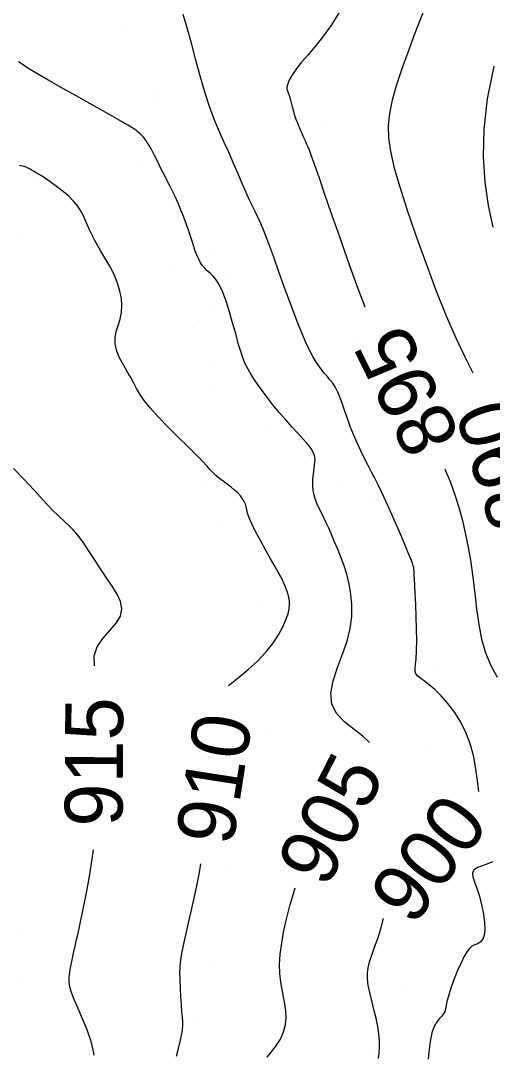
# Model space of a CAD drawing. Extents: x 400243 to 403697, y 4403637 to 4408083.
# Drawn here: x 402798.8 to 402859.8, y 4405855.9 to 4405990.3 of the extents above; entities that cross this region are included whole.
import ezdxf

# ---------------------------------------------------------------- set-up
doc = ezdxf.new("R2010")
doc.units = 0
doc.layers.add('HH_IC', color=7, linetype='Continuous')

msp = doc.modelspace()

# ---------------------------------------------------------------- linework, layer by layer
at = {"layer": 'HH_IC'}
for p, q in [((402812.27, 4405988.94), (402812.27, 4405988.94)), ((402816.11, 4405980.93), (402816.11, 4405980.93)), ((402815.81, 4405979.95), (402815.81, 4405979.95)), ((402838.18, 4405977.03), (402838.18, 4405977.03)), ((402814.25, 4405971.9), (402814.25, 4405971.9)), ((402818.19, 4405970.9), (402818.19, 4405970.9)), ((402800.36, 4405969.95), (402800.36, 4405969.95)), ((402818.38, 4405966.59), (402818.38, 4405966.59)), ((402799.14, 4405962.19), (402799.14, 4405962.19)), ((402823.27, 4405959.95), (402823.27, 4405959.95)), ((402818.45, 4405958.62), (402818.45, 4405958.62)), ((402825.28, 4405957.48), (402825.28, 4405957.48)), ((402823.89, 4405952.9), (402823.89, 4405952.9)), ((402821.03, 4405950.54), (402821.03, 4405950.54)), ((402842.61, 4405948.63), (402842.61, 4405948.63)), ((402823.74, 4405945.88), (402823.74, 4405945.88)), ((402827.64, 4405944.76), (402827.64, 4405944.76)), ((402823.91, 4405942.35), (402823.91, 4405942.35)), ((402830.4, 4405937.76), (402830.4, 4405937.76)), ((402836.25, 4405934.4), (402836.25, 4405934.4)), ((402836.43, 4405933.89), (402836.43, 4405933.89)), ((402822.29, 4405930.07), (402822.29, 4405930.07)), ((402840.28, 4405930.62), (402840.28, 4405930.62)), ((402844.25, 4405927.85), (402844.25, 4405927.85)), ((402824.75, 4405925.05), (402824.75, 4405925.05)), ((402849.34, 4405919.6), (402849.34, 4405919.6)), ((402829.84, 4405914.78), (402829.84, 4405914.78)), ((402852.03, 4405906.66), (402852.03, 4405906.66)), ((402830.64, 4405898.69), (402830.64, 4405898.69)), ((402851.82, 4405896.2), (402851.82, 4405896.2)), ((402854.65, 4405887.27), (402854.65, 4405887.27)), ((402853.82, 4405881.5), (402853.82, 4405881.5)), ((402825.87, 4405881.03), (402825.87, 4405881.03)), ((402852.28, 4405874.06), (402852.28, 4405874.06)), ((402799.03, 4405872.77), (402799.03, 4405872.77)), ((402824, 4405868.48), (402824, 4405868.48)), ((402798.89, 4405866.14), (402798.89, 4405866.14)), ((402848.24, 4405865.54), (402848.24, 4405865.54)), ((402821.33, 4405860.55), (402821.33, 4405860.55)), ((402843.88, 4405856.71), (402843.88, 4405856.71))]:
    msp.add_line(p, q, dxfattribs=at)
for points in [[(402858.07, 4405890.54), (402857.93, 4405891.93), (402857.72, 4405893.43), (402857.42, 4405894.99), (402857.01, 4405896.55), (402856.46, 4405898.07), (402855.76, 4405899.48), (402854.96, 4405900.76), (402854.09, 4405901.91), (402853.23, 4405902.89), (402852.41, 4405903.7), (402851.68, 4405904.33), (402851.06, 4405904.8), (402850.56, 4405905.16), (402850.18, 4405905.46), (402849.94, 4405905.74), (402849.83, 4405906.04), (402849.83, 4405906.42), (402849.89, 4405906.95), (402849.97, 4405907.7), (402850.04, 4405908.72), (402850.06, 4405910.04), (402850.04, 4405911.58), (402849.98, 4405913.18), (402849.92, 4405914.74), (402849.85, 4405916.1), (402849.8, 4405917.17), (402849.76, 4405917.98), (402849.73, 4405918.56), (402849.7, 4405918.97), (402849.68, 4405919.27), (402849.66, 4405919.5), (402849.6, 4405919.74), (402849.49, 4405920.08), (402849.29, 4405920.61), (402848.96, 4405921.4), (402848.5, 4405922.5), (402847.94, 4405923.84), (402847.31, 4405925.3), (402846.67, 4405926.75), (402846.07, 4405928.09), (402845.54, 4405929.22), (402845.06, 4405930.19), (402844.62, 4405931.05), (402844.2, 4405931.86), (402843.76, 4405932.71), (402843.29, 4405933.63), (402842.81, 4405934.62), (402842.33, 4405935.65), (402841.87, 4405936.7), (402841.45, 4405937.75), (402841.09, 4405938.77), (402840.76, 4405939.74), (402840.45, 4405940.65), (402840.15, 4405941.47), (402839.85, 4405942.2), (402839.52, 4405942.82), (402839.17, 4405943.35), (402838.82, 4405943.81), (402838.45, 4405944.25), (402838.08, 4405944.67), (402837.72, 4405945.12), (402837.36, 4405945.61), (402836.98, 4405946.17), (402836.59, 4405946.83), (402836.18, 4405947.62), (402835.74, 4405948.55), (402835.26, 4405949.64), (402834.74, 4405950.91), (402834.17, 4405952.36), (402833.56, 4405954), (402832.9, 4405955.83), (402832.21, 4405957.76), (402831.54, 4405959.65), (402830.9, 4405961.39), (402830.35, 4405962.87), (402829.88, 4405964), (402829.49, 4405964.86), (402829.14, 4405965.58), (402828.79, 4405966.27), (402828.41, 4405967.06), (402827.97, 4405968.04), (402827.47, 4405969.18), (402826.92, 4405970.44), (402826.35, 4405971.78), (402825.75, 4405973.15), (402825.13, 4405974.51), (402824.51, 4405975.9), (402823.89, 4405977.4), (402823.26, 4405979.04), (402822.65, 4405980.88), (402822.04, 4405982.96), (402821.45, 4405985.16), (402820.88, 4405987.34), (402820.33, 4405989.36), (402819.81, 4405991.06)], [(402840, 4405991.33), (402838.92, 4405989.61), (402837.85, 4405988.14), (402836.85, 4405986.89), (402835.93, 4405985.82), (402835.15, 4405984.9), (402834.52, 4405984.1), (402834.04, 4405983.41), (402833.68, 4405982.82), (402833.44, 4405982.34), (402833.3, 4405981.95), (402833.24, 4405981.65), (402833.24, 4405981.41), (402833.3, 4405981.18), (402833.4, 4405980.92), (402833.52, 4405980.59), (402833.65, 4405980.16), (402833.79, 4405979.65), (402833.93, 4405979.1), (402834.08, 4405978.54), (402834.24, 4405978.01), (402834.39, 4405977.54), (402834.55, 4405977.13), (402834.71, 4405976.75), (402834.87, 4405976.39), (402835.02, 4405976.05), (402835.18, 4405975.7), (402835.32, 4405975.36), (402835.46, 4405975.04), (402835.59, 4405974.75), (402835.7, 4405974.5), (402835.8, 4405974.29), (402835.92, 4405974.01), (402836.11, 4405973.55), (402836.4, 4405972.79), (402836.82, 4405971.6), (402837.41, 4405969.92), (402838.13, 4405967.83), (402838.95, 4405965.46), (402839.82, 4405962.95), (402840.7, 4405960.42), (402841.55, 4405957.98), (402842.41, 4405955.6), (402843.32, 4405953.24)], [(402850.87, 4405991.37), (402849.82, 4405988.66), (402848.88, 4405986.17), (402848.07, 4405983.9), (402847.4, 4405981.84), (402846.89, 4405979.97), (402846.54, 4405978.27), (402846.37, 4405976.69), (402846.4, 4405975.11), (402846.64, 4405973.39), (402847.1, 4405971.36), (402847.81, 4405968.89), (402848.77, 4405965.88), (402849.93, 4405962.48), (402851.21, 4405958.91), (402852.54, 4405955.38), (402853.86, 4405952.09), (402855.11, 4405949.23), (402856.27, 4405946.78), (402857.32, 4405944.68)], [(402843.93, 4405896.87), (402843.06, 4405897.69), (402841.93, 4405898.55), (402840.75, 4405899.5), (402839.72, 4405900.57), (402839.07, 4405901.82), (402838.94, 4405903.26), (402839.24, 4405904.86), (402839.8, 4405906.55), (402840.45, 4405908.28), (402841.04, 4405909.99), (402841.44, 4405911.63), (402841.63, 4405913.18), (402841.65, 4405914.66), (402841.53, 4405916.07), (402841.3, 4405917.4), (402840.98, 4405918.66), (402840.61, 4405919.85), (402840.2, 4405920.96), (402839.78, 4405921.98), (402839.38, 4405922.93), (402839, 4405923.79), (402838.66, 4405924.58), (402838.34, 4405925.3), (402838.03, 4405925.95), (402837.73, 4405926.57), (402837.44, 4405927.14), (402837.17, 4405927.7), (402836.94, 4405928.26), (402836.75, 4405928.85), (402836.64, 4405929.48), (402836.6, 4405930.18), (402836.62, 4405930.91), (402836.68, 4405931.62), (402836.76, 4405932.26), (402836.82, 4405932.8), (402836.86, 4405933.2), (402836.88, 4405933.48), (402836.87, 4405933.68), (402836.84, 4405933.83), (402836.8, 4405933.98), (402836.75, 4405934.16), (402836.66, 4405934.38), (402836.5, 4405934.68), (402836.24, 4405935.06), (402835.86, 4405935.55), (402835.32, 4405936.17), (402834.65, 4405936.89), (402833.9, 4405937.71), (402833.09, 4405938.6), (402832.25, 4405939.57), (402831.43, 4405940.57), (402830.64, 4405941.59), (402829.9, 4405942.59), (402829.24, 4405943.54), (402828.68, 4405944.4), (402828.23, 4405945.16), (402827.86, 4405945.87), (402827.55, 4405946.62), (402827.26, 4405947.47), (402826.95, 4405948.51), (402826.61, 4405949.77), (402826.22, 4405951.17), (402825.82, 4405952.61), (402825.39, 4405953.98), (402824.95, 4405955.15), (402824.52, 4405956.06), (402824.09, 4405956.73), (402823.68, 4405957.22), (402823.29, 4405957.59), (402822.93, 4405957.91), (402822.61, 4405958.23), (402822.33, 4405958.56), (402822.06, 4405958.95), (402821.82, 4405959.4), (402821.58, 4405959.94), (402821.34, 4405960.59), (402821.1, 4405961.33), (402820.84, 4405962.14), (402820.56, 4405963.01), (402820.25, 4405963.91), (402819.9, 4405964.84), (402819.53, 4405965.76), (402819.15, 4405966.66), (402818.76, 4405967.51), (402818.39, 4405968.3), (402818.04, 4405969), (402817.71, 4405969.64), (402817.39, 4405970.26), (402817.06, 4405970.88), (402816.74, 4405971.54), (402816.39, 4405972.26), (402816.03, 4405973.01), (402815.64, 4405973.76), (402815.2, 4405974.48), (402814.72, 4405975.13), (402814.17, 4405975.69), (402813.5, 4405976.21), (402812.64, 4405976.76), (402811.53, 4405977.41), (402810.1, 4405978.2), (402808.32, 4405979.19), (402806.34, 4405980.31), (402804.32, 4405981.46), (402802.43, 4405982.54), (402800.85, 4405983.45), (402799.71, 4405984.14), (402798.95, 4405984.62), (402798.48, 4405984.94)], [(402859.94, 4405963.54), (402859.36, 4405966.35), (402858.92, 4405969.38), (402858.7, 4405972.65), (402858.78, 4405976.23), (402859.22, 4405980.14), (402860.07, 4405984.37)], [(402825.68, 4405904.25), (402826.93, 4405905.24), (402828.22, 4405906.29), (402829.45, 4405907.39), (402830.52, 4405908.53), (402831.41, 4405909.67), (402832.14, 4405910.78), (402832.7, 4405911.81), (402833.12, 4405912.73), (402833.39, 4405913.5), (402833.54, 4405914.16), (402833.59, 4405914.71), (402833.57, 4405915.18), (402833.5, 4405915.61), (402833.4, 4405916.02), (402833.28, 4405916.39), (402833.15, 4405916.75), (402833.01, 4405917.08), (402832.88, 4405917.38), (402832.76, 4405917.66), (402832.61, 4405917.98), (402832.41, 4405918.38), (402832.11, 4405918.92), (402831.69, 4405919.67), (402831.13, 4405920.65), (402830.48, 4405921.8), (402829.82, 4405922.99), (402829.19, 4405924.15), (402828.69, 4405925.16), (402828.35, 4405925.94), (402828.15, 4405926.54), (402828.04, 4405926.99), (402827.96, 4405927.36), (402827.87, 4405927.69), (402827.72, 4405928.04), (402827.5, 4405928.4), (402827.23, 4405928.77), (402826.88, 4405929.15), (402826.47, 4405929.53), (402826.01, 4405929.91), (402825.5, 4405930.29), (402824.99, 4405930.67), (402824.5, 4405931.04), (402824.06, 4405931.4), (402823.68, 4405931.76), (402823.31, 4405932.16), (402822.86, 4405932.66), (402822.27, 4405933.3), (402821.46, 4405934.14), (402820.38, 4405935.2), (402819.14, 4405936.43), (402817.83, 4405937.72), (402816.59, 4405938.99), (402815.54, 4405940.15), (402814.76, 4405941.12), (402814.2, 4405941.94), (402813.79, 4405942.68), (402813.43, 4405943.38), (402813.05, 4405944.1), (402812.58, 4405944.89), (402812.07, 4405945.75), (402811.59, 4405946.63), (402811.21, 4405947.52), (402811, 4405948.39), (402811, 4405949.22), (402811.16, 4405950.03), (402811.41, 4405950.83), (402811.66, 4405951.65), (402811.84, 4405952.5), (402811.88, 4405953.4), (402811.81, 4405954.33), (402811.63, 4405955.26), (402811.37, 4405956.16), (402811.06, 4405957.01), (402810.71, 4405957.77), (402810.34, 4405958.48), (402809.95, 4405959.15), (402809.56, 4405959.8), (402809.16, 4405960.46), (402808.77, 4405961.14), (402808.39, 4405961.84), (402808.03, 4405962.53), (402807.7, 4405963.22), (402807.4, 4405963.88), (402807.13, 4405964.51), (402806.85, 4405965.11), (402806.54, 4405965.7), (402806.16, 4405966.28), (402805.67, 4405966.88), (402805.04, 4405967.5), (402804.33, 4405968.11), (402803.59, 4405968.68), (402802.9, 4405969.2), (402802.3, 4405969.62), (402801.86, 4405969.92), (402801.54, 4405970.13), (402801.32, 4405970.27), (402801.16, 4405970.37), (402801.01, 4405970.45), (402800.85, 4405970.54), (402800.69, 4405970.63), (402800.51, 4405970.73), (402800.34, 4405970.83), (402800.17, 4405970.94), (402800.01, 4405971.04), (402799.85, 4405971.14), (402799.67, 4405971.23), (402799.47, 4405971.31), (402799.23, 4405971.39), (402798.95, 4405971.45), (402798.62, 4405971.51)], [(402808.32, 4405906.8), (402808.27, 4405908.08), (402808.68, 4405909.25), (402809.43, 4405910.33), (402810.31, 4405911.34), (402811.13, 4405912.3), (402811.71, 4405913.23), (402811.89, 4405914.16), (402811.72, 4405915.09), (402811.27, 4405916.06), (402810.64, 4405917.08), (402809.89, 4405918.17), (402809.11, 4405919.34), (402808.33, 4405920.54), (402807.57, 4405921.71), (402806.85, 4405922.78), (402806.19, 4405923.68), (402805.59, 4405924.37), (402805.02, 4405924.95), (402804.41, 4405925.51), (402803.7, 4405926.17), (402802.82, 4405927.03), (402801.74, 4405928.17), (402800.51, 4405929.51), (402799.19, 4405930.92), (402797.86, 4405932.3)], [(402853.67, 4405932.25), (402854.36, 4405930.62), (402854.94, 4405929.04), (402855.45, 4405927.44), (402855.92, 4405925.76), (402856.34, 4405923.99), (402856.72, 4405922.13), (402857.05, 4405920.21), (402857.33, 4405918.22), (402857.56, 4405916.19), (402857.79, 4405914.15), (402858.07, 4405912.15), (402858.44, 4405910.24), (402858.95, 4405908.45), (402859.65, 4405906.82), (402860.46, 4405905.32)], [(402808.29, 4405856.42), (402808.26, 4405856.72), (402807.91, 4405858.19), (402807.39, 4405859.68), (402806.8, 4405861.12), (402806.22, 4405862.44), (402805.72, 4405863.59), (402805.37, 4405864.51), (402805.16, 4405865.26), (402805.06, 4405865.9), (402805.07, 4405866.51), (402805.14, 4405867.16), (402805.27, 4405867.91), (402805.43, 4405868.73), (402805.62, 4405869.6), (402805.82, 4405870.49), (402806.02, 4405871.36), (402806.21, 4405872.19), (402806.39, 4405873.01), (402806.58, 4405873.89), (402806.78, 4405874.85), (402807, 4405875.94), (402807.24, 4405877.2), (402807.5, 4405878.59), (402807.76, 4405880.05), (402808, 4405881.52), (402808.2, 4405882.96)], [(402818.95, 4405856.29), (402819.14, 4405856.94), (402819.48, 4405858.35), (402819.68, 4405859.39), (402819.77, 4405860.14), (402819.78, 4405860.74), (402819.73, 4405861.32), (402819.65, 4405862.01), (402819.58, 4405862.91), (402819.51, 4405863.96), (402819.45, 4405865.07), (402819.42, 4405866.13), (402819.4, 4405867.06), (402819.41, 4405867.79), (402819.45, 4405868.41), (402819.54, 4405869.03), (402819.7, 4405869.79), (402819.92, 4405870.8), (402820.21, 4405872.14), (402820.56, 4405873.71), (402820.92, 4405875.36), (402821.27, 4405876.95), (402821.57, 4405878.33), (402821.8, 4405879.41), (402821.96, 4405880.3), (402822.09, 4405881.17)], [(402859.91, 4405881.42), (402858.79, 4405881.01), (402857.93, 4405880.68), (402857.43, 4405880.34), (402857.25, 4405879.95), (402857.31, 4405879.46), (402857.53, 4405878.83), (402857.84, 4405878.01), (402858.16, 4405876.99), (402858.45, 4405875.84), (402858.68, 4405874.66), (402858.84, 4405873.55), (402858.88, 4405872.61), (402858.79, 4405871.9), (402858.59, 4405871.41), (402858.32, 4405871.08), (402858.02, 4405870.87), (402857.71, 4405870.74), (402857.43, 4405870.62), (402857.15, 4405870.46), (402856.87, 4405870.21), (402856.56, 4405869.81), (402856.2, 4405869.2), (402855.79, 4405868.36), (402855.34, 4405867.34), (402854.9, 4405866.26), (402854.5, 4405865.19), (402854.2, 4405864.23), (402854, 4405863.46), (402853.88, 4405862.86), (402853.79, 4405862.4), (402853.69, 4405862.03), (402853.53, 4405861.74), (402853.29, 4405861.46), (402852.98, 4405861.15), (402852.64, 4405860.73), (402852.3, 4405860.13), (402852.01, 4405859.29), (402851.78, 4405858.16), (402851.61, 4405856.8), (402851.52, 4405855.88)], [(402830.7, 4405856.14), (402831.08, 4405856.61), (402831.82, 4405857.56), (402832.42, 4405858.49), (402832.82, 4405859.41), (402833.05, 4405860.32), (402833.13, 4405861.23), (402833.09, 4405862.13), (402832.97, 4405863.03), (402832.8, 4405863.94), (402832.61, 4405864.88), (402832.44, 4405865.87), (402832.33, 4405866.95), (402832.3, 4405868.15), (402832.39, 4405869.48), (402832.57, 4405870.89), (402832.82, 4405872.31), (402833.11, 4405873.66), (402833.41, 4405874.87), (402833.68, 4405875.89), (402833.93, 4405876.74), (402834.13, 4405877.45), (402834.29, 4405878.07)], [(402845.09, 4405855.96), (402845.17, 4405856.6), (402845.22, 4405857.4), (402845.22, 4405858.25), (402845.15, 4405859.15), (402845, 4405860.13), (402844.78, 4405861.21), (402844.51, 4405862.33), (402844.22, 4405863.45), (402843.97, 4405864.51), (402843.77, 4405865.47), (402843.67, 4405866.29), (402843.67, 4405867.01), (402843.77, 4405867.72), (402843.95, 4405868.47), (402844.23, 4405869.33), (402844.59, 4405870.36), (402845, 4405871.52), (402845.39, 4405872.77), (402845.73, 4405874.07)]]:
    msp.add_lwpolyline(points, dxfattribs=at)

# ---------------------------------------------------------------- texts
for s, rotation, p in [('895', 116.2575, (402855.8, 4405936.42)), ('890', 107.2282, (402867.08, 4405925.88)), ('915', 89.7184, (402811.97, 4405885.96)), ('910', 81.1562, (402826.22, 4405883.34)), ('905', 62.8576, (402838.38, 4405877.83)), ('900', 53.1695, (402849.56, 4405872.93))]:
    msp.add_text(s, height=7.5, rotation=rotation, dxfattribs=at).set_placement(p)

doc.saveas('drawing.dxf')
